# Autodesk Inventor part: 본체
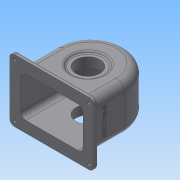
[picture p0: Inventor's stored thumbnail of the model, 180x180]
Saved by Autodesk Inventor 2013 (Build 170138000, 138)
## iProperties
Created: 2016-01
Part Number: 본체
Material: 일반
Document SubType Name: Modeling
Designer: Administrator
Density: 1 g/cm^3
Author: Administrator
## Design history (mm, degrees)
sketch "스케치1"
  geometry: L1 (-57, 0)-(-57, -64); L2 (57, 0)-(57, -64); L3 (-57, -64)-(57, -64); C1 r 51 at (0, 0); A1 r 57 centre (0, 0) between (57, 0) and (-57, 0); 1 further point
  constraints: 6 end point, 2 centre point, 2 parallel, 2 point on circle, 2 tangent, 1 coincident, 1 perpendicular, 1 vertical
  dimensions: "d0" = 51 radius of C1; "d1" = 6 radial gap between concentric circles of C1 A1; "d2" = 64 vertical distance of L1.end point (0, 0)
extrude "돌출1" new body sketch "스케치1" stored distance "d3" = 77; taper "d4" = 0 deg
sketch "스케치3"
  geometry: L1 (114, 0)-(114, -77) reference; L2 (0, 0)-(114, 0) reference; L3 (0, 0)-(0, -77) reference; L4 (114, -77)-(0, -77) reference; L5 (-13, -90.5)-(127, -90.5); L6 (127, -90.5)-(127, 13.5); L7 (127, 13.5)-(-13, 13.5); L8 (-13, 13.5)-(-13, -90.5); L9 (-13, -90.5)-(127, 13.5); L10 (127, -90.5)-(-13, 13.5); 1 further point
  constraints: 12 end point, 2 midpoint, 2 parallel, 1 horizontal, 1 perpendicular
  dimensions: "d9" = 140 distance of L7.end L6.end; "d10" = 104 distance of L6.end L5.end
extrude "돌출3" join sketch "스케치3" distance "d11" = 7; taper "d12" = 0 deg
feature "쉘1" dims "d13" = 7, "d14" = 5
sketch "스케치4"
  geometry: L1 (70, -64)-(-70, -64) reference; C1 r 31 at (0, -4); A1 r 57 centre (0, 0) between (57, 0) and (-57, 0) reference
  constraints: 1 centre point, 1 vertical alignment
  dimensions: "d40" = 62 diameter of C1; "d41" = 60 distance from line of L1 C1.centre
extrude "돌출4" join sketch "스케치4" distance "d16" = 10; taper "d17" = 0 deg
hole "구멍3" diameter "d44" = 40; stored, may be unused: countersink angle "d48" = 90 deg, drill point angle "d50" = 0 deg; dims "d42" = 10, "d43" = 10, "d45" = 6, "d46" = 4, "d47" = 2, "d49" = 15
sketch "스케치6"
  geometry: C1 r 20 at (0, 0) reference; 2 further points
  constraints: 1 vertical alignment
  dimensions: "d51" = 24 distance of C1.centre point (0, 24)
hole "구멍4" sketch "스케치6" at (0, 24) diameter "d52" = 2.459; stored, may be unused: countersink angle "d56" = 90 deg, drill point angle "d58" = 0 deg; dims "d53" = 6, "d54" = 4, "d55" = 2, "d57" = 8
fillet "모깎기1" dims "d66" = 14
fillet "모깎기2" dims "d67" = 9
fillet "모깎기3" dims "d68" = 8
node "작업 평면1"
node "작업 평면2"
sketch "스케치11"
  geometry: C1 r 6 at (0, 0); 1 further point
  constraints: 1 centre point, 1 coincident
  dimensions: "d71" = 12 diameter of C1
extrude "돌출5" join sketch "스케치11" stored distance "d72" = 6; taper "d73" = 0 deg
fillet "모깎기4" dims "d74" = 3
hole "구멍5" diameter "d77" = 4.459; stored, may be unused: countersink angle "d81" = 90 deg, drill point angle "d83" = 118 deg; dims "d75" = 10, "d76" = 10, "d78" = 6, "d79" = 4, "d80" = 2, "d82" = 19
sketch "스케치12"
  geometry: A1 r 8 centre (-5, 82.5) between (-5, 90.5) and (-13, 82.5) reference; A2 r 8 centre (-5, -5.5) between (-13, -5.5) and (-5, -13.5) reference; A3 r 8 centre (119, -5.5) between (119, -13.5) and (127, -5.5) reference; A4 r 8 centre (119, 82.5) between (127, 82.5) and (119, 90.5) reference; 5 further points
  constraints: 4 coincident
hole "구멍6" sketch "스케치12" at (-5, 82.5), (-5, -5.5), (119, -5.5), (119, 82.5) diameter "d84" = 5; stored, may be unused: countersink angle "d88" = 90 deg, drill point angle "d90" = 118 deg; dims "d85" = 6, "d86" = 4, "d87" = 2, "d89" = 19
fillet "모깎기5" dims "d91" = 3
fillet "모깎기6" dims "d92" = 1
sketch "스케치13"
  geometry: L1 (0, 0)-(49, 0) reference; L2 (68.5, -64)-(-19.5, -64) reference; 3 further points
  constraints: 1 midpoint, 1 vertical alignment, 1 other
  dimensions: "d93" = 30 distance from line of L2 point (24.5, -34)
feature "엠보싱1" sketch "스케치13" dims "d0" = 51, "d1" = 6, "d2" = 64, "d94" = 0.5, "d95" = 0
node "작업 평면3"
sketch "스케치14"
  geometry: C1 r 28 at (0, 0); 1 further point
  constraints: 1 centre point, 1 coincident
  dimensions: "d97" = 56 diameter of C1
extrude "돌출6" join sketch "스케치14" stored distance "d98" = 10; taper "d99" = 40 deg
node "작업 평면4"
sketch "스케치19"
  geometry: L1 (62, -64)-(-62, -64) reference; C1 r 28 at (0, -4); A1 r 43 centre (0, 0) between (43, 0) and (-43, 0) reference
  constraints: 1 centre point, 1 vertical alignment
  dimensions: "d109" = 56 diameter of C1; "d110" = 60 distance from line of L1 C1.centre
extrude "돌출7" cut sketch "스케치19" distance "d111" = 3; taper "d112" = 0 deg
fillet "모깎기7" dims "d113" = 3
sketch "스케치20"
  geometry: C1 r 25 at (0, 0) reference; 2 further points
  constraints: 1 coincident
hole "구멍7" sketch "스케치20" at (0, 0) diameter "d114" = 40; stored, may be unused: countersink angle "d118" = 90 deg, drill point angle "d120" = 0 deg; dims "d115" = 6, "d116" = 4, "d117" = 2, "d119" = 8
node "솔리드1"
pattern_circular "원형 패턴2" dims angle "d60" = 360 deg
other parameters: "d70" = 6, "d96" = 19.5, "d100" = 35.5
